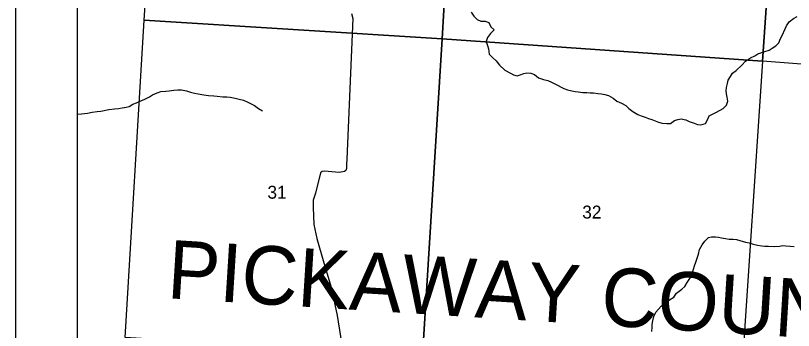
# Model space of a CAD drawing. Extents: x 0 to 42.5, y 0 to 22.
# Drawn here: x 2 to 3.26, y 16.014 to 16.524 of the extents above; entities that cross this region are included whole.
import ezdxf

# ---------------------------------------------------------------- set-up
doc = ezdxf.new("R2010")
doc.units = 0
for name, color, linetype in [('GM_X_County_Text', 7, 'Continuous'), ('GM_X_Interchange_Ramps', 7, 'Continuous'), ('GM_X_Minor_River', 7, 'Continuous'), ('GM_X_Section', 7, 'Continuous'), ('GM_X_Section_Text', 7, 'Continuous'), ('GM_X_Township_Road', 7, 'Continuous'), ('SH_Cut_Line', 7, 'Continuous'), ('SH_Data', 7, 'Continuous')]:
    doc.layers.add(name, color=color, linetype=linetype)

msp = doc.modelspace()

# ---------------------------------------------------------------- linework, layer by layer
at = {"layer": 'GM_X_Interchange_Ramps'}
msp.add_lwpolyline([(3.3708, 18.9861), (3.12, 19.001), (2.9496, 19.012), (2.741, 19.0247), (2.6729, 19.0297), (2.6231, 19.0318), (2.5272, 19.0385), (2.4885, 19.0403), (2.4656, 19.0429), (2.4593, 19.0431), (2.3672, 19.046), (2.1, 19.059), (2.1, 16.0076)], dxfattribs=at)
at = {"layer": 'GM_X_Minor_River'}
for points in [[(2.7381, 16.5295), (2.742, 16.5232), (2.7478, 16.5174), (2.7535, 16.5147), (2.7603, 16.5148), (2.7666, 16.513), (2.7699, 16.5057), (2.775, 16.5009), (2.7694, 16.4951), (2.7642, 16.4887), (2.762, 16.4822), (2.7641, 16.4754), (2.7659, 16.47), (2.7671, 16.4616), (2.7722, 16.4559), (2.7782, 16.4506), (2.784, 16.4435), (2.7924, 16.4358), (2.8015, 16.4306), (2.8066, 16.4278), (2.8123, 16.4264), (2.8172, 16.4279), (2.8231, 16.4303), (2.8279, 16.4314), (2.8347, 16.4307), (2.8404, 16.4284), (2.8468, 16.423), (2.8549, 16.4206), (2.8621, 16.4188), (2.868, 16.4161), (2.8746, 16.4127), (2.8878, 16.4059), (2.8941, 16.4039), (2.9009, 16.4021), (2.9062, 16.4011), (2.9113, 16.4003), (2.9187, 16.3996), (2.9253, 16.3992), (2.9305, 16.3991), (2.9362, 16.3987), (2.943, 16.3976), (2.9489, 16.397), (2.9542, 16.3963), (2.96, 16.3944), (2.968, 16.3901), (2.974, 16.3856), (2.9813, 16.3819), (2.9881, 16.3786), (2.993, 16.3736), (2.9994, 16.3684), (3.0077, 16.3639), (3.013, 16.3614), (3.0194, 16.3592), (3.0251, 16.3572), (3.0304, 16.3558), (3.0359, 16.3533), (3.0412, 16.3515), (3.0471, 16.3499), (3.0545, 16.3493), (3.0607, 16.3492), (3.0674, 16.3539), (3.0724, 16.3559), (3.0779, 16.3568), (3.0853, 16.355), (3.0908, 16.3522)], [(3.0908, 16.3522), (3.0991, 16.3495), (3.1046, 16.3475), (3.1099, 16.3469), (3.1171, 16.3493), (3.1206, 16.3551), (3.1232, 16.3614), (3.1287, 16.3645), (3.1343, 16.3671), (3.1409, 16.3706), (3.1457, 16.3734), (3.1513, 16.3791), (3.1533, 16.3855), (3.1524, 16.3918), (3.1515, 16.3972), (3.1508, 16.4021), (3.1511, 16.4074), (3.1529, 16.4139), (3.1542, 16.4192), (3.1581, 16.4254), (3.161, 16.4305), (3.1668, 16.4352), (3.1762, 16.4435), (3.1823, 16.4504), (3.19, 16.4558), (3.1973, 16.459), (3.2022, 16.462), (3.2133, 16.4656), (3.2204, 16.468), (3.2255, 16.4712), (3.2314, 16.4749), (3.2363, 16.4798), (3.239, 16.4868), (3.2417, 16.4917), (3.2464, 16.5023), (3.2484, 16.5074), (3.2526, 16.5139), (3.2597, 16.5195), (3.2656, 16.5226)], [(2.2435, 16.4017), (2.2487, 16.402), (2.2561, 16.4033), (2.2626, 16.4037), (2.2686, 16.4039), (2.277, 16.4022), (2.2832, 16.4001), (2.29, 16.3981), (2.2957, 16.3971), (2.3048, 16.3956), (2.3126, 16.3944), (2.3209, 16.3939), (2.3266, 16.3934), (2.3357, 16.3926), (2.342, 16.3923), (2.3477, 16.3917), (2.3557, 16.3902), (2.3623, 16.3884), (2.3689, 16.3868), (2.3759, 16.3837), (2.3818, 16.3811), (2.387, 16.3784), (2.3934, 16.3736), (2.3998, 16.3697)], [(2.1, 16.364), (2.1009, 16.3641), (2.1067, 16.3648), (2.1166, 16.3662), (2.1241, 16.3676), (2.1322, 16.3688), (2.1381, 16.3691), (2.1509, 16.372), (2.1604, 16.3732), (2.1665, 16.3737), (2.1726, 16.3746), (2.1792, 16.3755), (2.184, 16.3769), (2.1901, 16.3803), (2.1956, 16.3825), (2.2019, 16.3851), (2.2096, 16.3886), (2.217, 16.3925), (2.222, 16.3955), (2.2293, 16.3986), (2.2354, 16.4008), (2.2435, 16.4017)], [(3.0303, 16.0123), (3.0308, 16.0189), (3.031, 16.0237), (3.0318, 16.0294), (3.0338, 16.0364), (3.0371, 16.0434), (3.041, 16.0483), (3.0456, 16.0532), (3.0525, 16.0586), (3.0592, 16.0637), (3.0659, 16.0679), (3.0702, 16.0744), (3.0788, 16.0811), (3.0838, 16.0854), (3.0877, 16.0915), (3.0908, 16.0967), (3.095, 16.1028), (3.0978, 16.1134), (3.0996, 16.1189), (3.1019, 16.1244), (3.1041, 16.131), (3.1059, 16.1375), (3.1079, 16.145), (3.1121, 16.1528), (3.1162, 16.1586), (3.122, 16.1645), (3.1271, 16.1657), (3.1336, 16.1657), (3.1383, 16.165), (3.1432, 16.1638), (3.1499, 16.1628), (3.1557, 16.162), (3.1624, 16.1617), (3.1675, 16.1611), (3.1732, 16.1595), (3.1821, 16.1571), (3.1883, 16.1557), (3.1948, 16.1537), (3.2016, 16.1521), (3.2086, 16.1512), (3.2137, 16.1506), (3.2194, 16.1503), (3.2285, 16.15), (3.2371, 16.1507), (3.2426, 16.1514), (3.2473, 16.1511), (3.2547, 16.1507), (3.261, 16.1498)]]:
    msp.add_lwpolyline(points, dxfattribs=at)
at = {"layer": 'GM_X_Section'}
for points in [[(2.2424, 17.0272), (2.7205, 16.9974), (2.6908, 16.4865), (2.2084, 16.5167), (2.2418, 17.0185)], [(3.2447, 16.9606), (3.2094, 16.4499), (2.6908, 16.4865), (2.7205, 16.9974)], [(3.7577, 16.9327), (3.7198, 16.4108), (3.2094, 16.4499), (3.2447, 16.9606)], [(2.2084, 16.5167), (2.6908, 16.4865), (2.659, 15.973), (2.6533, 15.9734), (2.1775, 16.0023)], [(2.6908, 16.4865), (3.2094, 16.4499), (3.1757, 15.9403), (2.659, 15.973)]]:
    msp.add_lwpolyline(points, close=True, dxfattribs=at)
at = {"layer": 'GM_X_Township_Road'}
msp.add_lwpolyline([(2.5439, 16.5273), (2.5464, 16.5195), (2.5365, 16.2916), (2.5359, 16.2832), (2.5358, 16.2764), (2.5348, 16.2728), (2.5328, 16.2712), (2.524, 16.2698), (2.5001, 16.2718), (2.4965, 16.2716), (2.494, 16.2693), (2.486, 16.2362), (2.4821, 16.2248), (2.4818, 16.2134), (2.4832, 16.1856), (2.4881, 16.1627), (2.4995, 16.1236), (2.5113, 16.0839), (2.5208, 16.0382), (2.5298, 15.9802)], dxfattribs=at)
at = {"layer": 'SH_Cut_Line'}
msp.add_lwpolyline([(5.4888, 19.405), (5.5006, 19.5525), (5.5106, 19.6694), (5.5156, 19.736), (5.5253, 19.8538), (5.5354, 19.9847), (5.5461, 20.1166), (5.5647, 20.3456), (5.5656, 20.355), (5.5659, 20.3573), (5.6025, 20.8068), (5.6096, 20.9), (2.1, 20.9), (2.1, 16.0076)], dxfattribs=at)
at = {"layer": 'SH_Data'}
for p, q in [((2, 21), (2, 14)), ((2.1, 20.9), (2.1, 14.1))]:
    msp.add_line(p, q, dxfattribs=at)

# ---------------------------------------------------------------- texts
at = {"layer": 'GM_X_County_Text'}
msp.add_text('PICKAWAY COUNTY', height=0.094697, rotation=356.446, dxfattribs=at).set_placement((2.244, 16.0663))
at = {"layer": 'GM_X_Section_Text'}
for s, p in [('31', (2.4079, 16.2274)), ('32', (2.9177, 16.1953))]:
    msp.add_text(s, height=0.02093, rotation=0, dxfattribs=at).set_placement(p)

doc.saveas('drawing.dxf')
